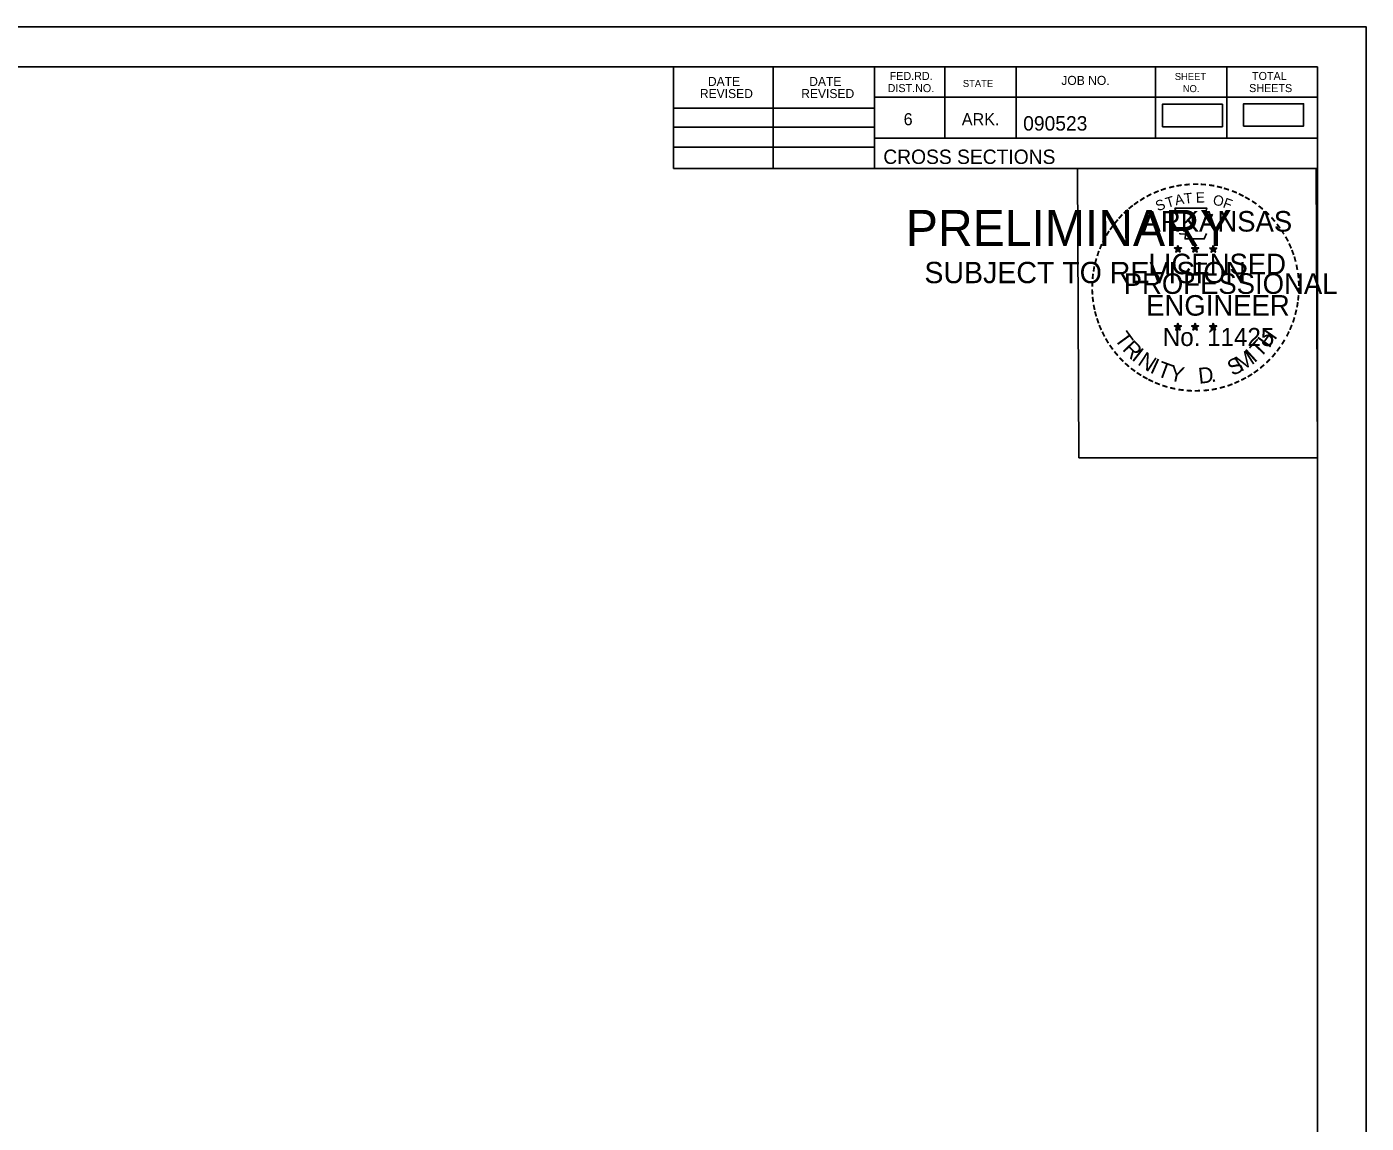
# Model space of a CAD drawing. Extents: x 1406028 to 1412453, y 321733 to 325986.
# Drawn here: x 1406230.5 to 1406360.9, y 322252.5 to 322359.2 of the extents above; entities that cross this region are included whole.
import ezdxf

# ---------------------------------------------------------------- set-up
doc = ezdxf.new("R2010")
doc.units = 0
for name, color, linetype in [('R_Border', 7, 'Continuous'), ('R_Border PE', 7, 'Continuous'), ('R_Border Prem', 7, 'Continuous'), ('R_Fin Surface', 7, 'Continuous'), ('R_No Plot', 7, 'Continuous')]:
    doc.layers.add(name, color=color, linetype=linetype)

msp = doc.modelspace()

# ---------------------------------------------------------------- linework, layer by layer
at = {"layer": 'R_Border'}
for p, q in [((1406039.95, 322355.29), (1406356.13, 322355.29)), ((1406293.49, 322345.41), (1406293.49, 322355.29)), ((1406303.17, 322345.41), (1406303.17, 322355.29)), ((1406313.03, 322355.29), (1406313.03, 322345.41)), ((1406319.87, 322355.29), (1406319.87, 322348.35)), ((1406326.81, 322355.29), (1406326.81, 322348.35)), ((1406340.39, 322355.29), (1406340.39, 322348.35)), ((1406347.33, 322355.29), (1406347.33, 322348.35)), ((1406356.13, 322149.83), (1406356.13, 322355.29)), ((1406356.13, 322352.35), (1406313.03, 322352.35)), ((1406356.13, 322352.37), (1406356.13, 322352.37)), ((1406293.49, 322351.27), (1406313.03, 322351.27)), ((1406293.49, 322349.41), (1406313.03, 322349.41)), ((1406356.13, 322348.35), (1406313.03, 322348.35)), ((1406315.99, 322348.35), (1406356.13, 322348.35)), ((1406293.49, 322347.47), (1406313.03, 322347.47)), ((1406356.13, 322345.41), (1406293.49, 322345.41))]:
    msp.add_line(p, q, dxfattribs=at)
at = {"layer": 'R_Border PE'}
for p, q in [((1406342.21, 322337.67), (1406342.56, 322337.55)), ((1406342.21, 322337.67), (1406342.47, 322337.62)), ((1406342.21, 322337.67), (1406342.45, 322337.54)), ((1406342.56, 322337.92), (1406342.52, 322337.67)), ((1406342.56, 322337.55), (1406342.56, 322337.92)), ((1406342.56, 322337.92), (1406342.61, 322337.67)), ((1406342.91, 322337.67), (1406342.56, 322337.55)), ((1406342.91, 322337.67), (1406342.62, 322337.62)), ((1406342.91, 322337.67), (1406342.7, 322337.56)), ((1406343.88, 322337.67), (1406344.23, 322337.55)), ((1406343.88, 322337.67), (1406344.14, 322337.62)), ((1406343.88, 322337.67), (1406344.12, 322337.54)), ((1406344.23, 322337.92), (1406344.19, 322337.67)), ((1406344.23, 322337.55), (1406344.23, 322337.92)), ((1406344.23, 322337.92), (1406344.28, 322337.67)), ((1406344.58, 322337.67), (1406344.23, 322337.55)), ((1406344.58, 322337.67), (1406344.29, 322337.62)), ((1406344.58, 322337.67), (1406344.37, 322337.56)), ((1406345.65, 322337.65), (1406346, 322337.54)), ((1406345.65, 322337.65), (1406345.9, 322337.61)), ((1406345.65, 322337.65), (1406345.88, 322337.53)), ((1406346, 322337.91), (1406345.95, 322337.66)), ((1406346, 322337.54), (1406346, 322337.91)), ((1406346, 322337.91), (1406346.04, 322337.66)), ((1406346.34, 322337.65), (1406346, 322337.54)), ((1406346.34, 322337.65), (1406346.06, 322337.6)), ((1406346.34, 322337.65), (1406346.14, 322337.55)), ((1406342.35, 322337.26), (1406342.56, 322337.55)), ((1406342.35, 322337.26), (1406342.47, 322337.5)), ((1406342.35, 322337.26), (1406342.56, 322337.47)), ((1406342.77, 322337.26), (1406342.56, 322337.55)), ((1406342.77, 322337.26), (1406342.56, 322337.47)), ((1406342.77, 322337.26), (1406342.64, 322337.55)), ((1406344.02, 322337.26), (1406344.23, 322337.55)), ((1406344.02, 322337.26), (1406344.14, 322337.5)), ((1406344.02, 322337.26), (1406344.23, 322337.47)), ((1406344.44, 322337.26), (1406344.23, 322337.55)), ((1406344.44, 322337.26), (1406344.23, 322337.47)), ((1406344.44, 322337.26), (1406344.31, 322337.55)), ((1406345.78, 322337.25), (1406346, 322337.54)), ((1406345.78, 322337.25), (1406345.91, 322337.49)), ((1406345.78, 322337.25), (1406345.99, 322337.46)), ((1406346.21, 322337.25), (1406345.99, 322337.46)), ((1406346.21, 322337.25), (1406346, 322337.54)), ((1406346.21, 322337.25), (1406346.07, 322337.54)), ((1406342.21, 322330.09), (1406342.56, 322329.98)), ((1406342.21, 322330.09), (1406342.46, 322330.05)), ((1406342.21, 322330.09), (1406342.45, 322329.97)), ((1406342.34, 322329.68), (1406342.56, 322329.98)), ((1406342.34, 322329.68), (1406342.47, 322329.93)), ((1406342.34, 322329.68), (1406342.56, 322329.9)), ((1406342.56, 322330.35), (1406342.52, 322330.09)), ((1406342.56, 322329.98), (1406342.56, 322330.35)), ((1406342.56, 322330.35), (1406342.61, 322330.1)), ((1406342.9, 322330.09), (1406342.56, 322329.98)), ((1406342.77, 322329.68), (1406342.56, 322329.98)), ((1406342.77, 322329.68), (1406342.56, 322329.9)), ((1406342.9, 322330.09), (1406342.62, 322330.04)), ((1406342.77, 322329.68), (1406342.63, 322329.98)), ((1406342.9, 322330.09), (1406342.7, 322329.99)), ((1406343.88, 322330.09), (1406344.23, 322329.98)), ((1406343.88, 322330.09), (1406344.13, 322330.05)), ((1406343.88, 322330.09), (1406344.11, 322329.97)), ((1406344.01, 322329.68), (1406344.23, 322329.98)), ((1406344.01, 322329.68), (1406344.14, 322329.93)), ((1406344.01, 322329.68), (1406344.22, 322329.9)), ((1406344.23, 322330.35), (1406344.19, 322330.09)), ((1406344.44, 322329.68), (1406344.22, 322329.9)), ((1406344.23, 322329.98), (1406344.23, 322330.35)), ((1406344.23, 322330.35), (1406344.28, 322330.1)), ((1406344.57, 322330.09), (1406344.23, 322329.98)), ((1406344.44, 322329.68), (1406344.23, 322329.98)), ((1406344.57, 322330.09), (1406344.29, 322330.04)), ((1406344.44, 322329.68), (1406344.3, 322329.98)), ((1406344.57, 322330.09), (1406344.37, 322329.99)), ((1406345.64, 322330.08), (1406345.99, 322329.97)), ((1406345.64, 322330.08), (1406345.9, 322330.04)), ((1406345.64, 322330.08), (1406345.88, 322329.96)), ((1406345.78, 322329.67), (1406345.99, 322329.97)), ((1406345.78, 322329.67), (1406345.9, 322329.92)), ((1406345.78, 322329.67), (1406345.99, 322329.89)), ((1406345.99, 322330.34), (1406345.95, 322330.08)), ((1406345.99, 322329.97), (1406345.99, 322330.34)), ((1406345.99, 322330.34), (1406346.04, 322330.09)), ((1406346.34, 322330.08), (1406345.99, 322329.97)), ((1406346.21, 322329.67), (1406345.99, 322329.97)), ((1406346.21, 322329.67), (1406345.99, 322329.89)), ((1406346.34, 322330.08), (1406346.05, 322330.03)), ((1406346.21, 322329.67), (1406346.07, 322329.97)), ((1406346.34, 322330.08), (1406346.14, 322329.98))]:
    msp.add_line(p, q, dxfattribs=at)
for points in [[(1406342.25, 322341.54), (1406342.52, 322340.72)], [(1406345.76, 322340.62), (1406345.91, 322340.91), (1406345.22, 322340.88), (1406345.37, 322341.54), (1406342.25, 322341.54)], [(1406342.75, 322339.12), (1406342.75, 322339.03), (1406343.31, 322339.01), (1406343.25, 322338.54), (1406345.12, 322338.54), (1406345.33, 322339.08)], [(1406342.56, 322337.92), (1406342.77, 322337.26), (1406342.21, 322337.67), (1406342.91, 322337.67), (1406342.35, 322337.26), (1406342.56, 322337.92)], [(1406344.23, 322337.92), (1406344.44, 322337.26), (1406343.88, 322337.67), (1406344.58, 322337.67), (1406344.02, 322337.26), (1406344.23, 322337.92)], [(1406346, 322337.91), (1406346.21, 322337.25), (1406345.65, 322337.65), (1406346.34, 322337.65), (1406345.78, 322337.25), (1406346, 322337.91)], [(1406342.56, 322330.35), (1406342.77, 322329.68), (1406342.21, 322330.09), (1406342.9, 322330.09), (1406342.34, 322329.68), (1406342.56, 322330.35)], [(1406344.23, 322330.35), (1406344.44, 322329.68), (1406343.88, 322330.09), (1406344.57, 322330.09), (1406344.01, 322329.68), (1406344.23, 322330.35)], [(1406345.99, 322330.34), (1406346.21, 322329.67), (1406345.64, 322330.08), (1406346.34, 322330.08), (1406345.78, 322329.67), (1406345.99, 322330.34)]]:
    msp.add_lwpolyline(points, dxfattribs=at)
for centre, radius in [((1406342.56, 322337.55), 0.172), ((1406342.56, 322337.55), 0.145), ((1406342.56, 322337.55), 0.116), ((1406342.56, 322337.55), 0.0991), ((1406342.56, 322337.55), 0.0747), ((1406342.56, 322337.55), 0.0495), ((1406342.56, 322337.55), 0.0296), ((1406344.23, 322337.55), 0.172), ((1406344.23, 322337.55), 0.145), ((1406344.23, 322337.55), 0.116), ((1406344.23, 322337.55), 0.0991), ((1406344.23, 322337.55), 0.0747), ((1406344.23, 322337.55), 0.0495), ((1406344.23, 322337.55), 0.0296), ((1406345.99, 322337.54), 0.172), ((1406345.99, 322337.54), 0.145), ((1406345.99, 322337.54), 0.116), ((1406345.99, 322337.54), 0.0991), ((1406345.99, 322337.54), 0.0747), ((1406345.99, 322337.54), 0.0495), ((1406345.99, 322337.54), 0.0296), ((1406342.56, 322329.98), 0.172), ((1406342.56, 322329.98), 0.145), ((1406342.56, 322329.98), 0.116), ((1406342.56, 322329.98), 0.0991), ((1406342.56, 322329.98), 0.0747), ((1406342.56, 322329.98), 0.0495), ((1406342.56, 322329.98), 0.0296), ((1406344.23, 322329.98), 0.172), ((1406344.23, 322329.98), 0.145), ((1406344.23, 322329.98), 0.116), ((1406344.23, 322329.98), 0.0991), ((1406344.23, 322329.98), 0.0747), ((1406344.23, 322329.98), 0.0495), ((1406344.23, 322329.98), 0.0296), ((1406345.99, 322329.97), 0.172), ((1406345.99, 322329.97), 0.145), ((1406345.99, 322329.97), 0.116), ((1406345.99, 322329.97), 0.0991), ((1406345.99, 322329.97), 0.0747), ((1406345.99, 322329.97), 0.0495), ((1406345.99, 322329.97), 0.0296)]:
    msp.add_circle(centre, radius, dxfattribs=at)
at = {"layer": 'R_Fin Surface'}
for points in [[(1406341.05, 322349.46), (1406346.88, 322349.46), (1406346.88, 322351.65), (1406341.05, 322351.65)], [(1406348.94, 322349.52), (1406354.78, 322349.52), (1406354.78, 322351.7), (1406348.94, 322351.7)]]:
    msp.add_lwpolyline(points, close=True, dxfattribs=at)
at = {"layer": 'R_No Plot'}
for p, q in [((1406027.55, 322359.18), (1406360.88, 322359.18)), ((1406332.16, 322322.95), (1406332.16, 322322.95))]:
    msp.add_line(p, q, dxfattribs=at)
for points in [[(1406027.54, 322359.18), (1406360.88, 322359.18), (1406360.88, 322145.85), (1406027.54, 322145.85)], [(1406273.87, 322355.29), (1406293.49, 322355.29), (1406293.49, 322345.41), (1406309.6, 322345.41), (1406332.8, 322345.41), (1406332.92, 322317.25), (1406356.13, 322317.25), (1406356.13, 322149.83), (1406039.95, 322149.83), (1406039.95, 322355.29)], [(1406332.8, 322345.41), (1406356.01, 322345.41), (1406356.13, 322317.25), (1406332.92, 322317.25)]]:
    msp.add_lwpolyline(points, close=True, dxfattribs=at)

# ---------------------------------------------------------------- texts
at = {"layer": 'R_Border'}
for s, height, p in [('FED.RD.', 0.782, (1406314.51, 322354.01)), ('SHEET', 0.684, (1406342.25, 322354.01)), ('TOTAL', 0.782, (1406349.77, 322354.01)), ('DATE', 0.879, (1406296.82, 322353.43)), ('DATE', 0.879, (1406306.68, 322353.43)), ('DIST.NO.', 0.782, (1406314.31, 322352.83)), ('STATE', 0.684, (1406321.63, 322353.33)), ('JOB NO.', 0.879, (1406331.21, 322353.53)), ('NO.', 0.684, (1406343.03, 322352.83)), ('SHEETS', 0.782, (1406349.49, 322352.83)), ('REVISED', 0.879, (1406296.04, 322352.25)), ('REVISED', 0.879, (1406305.9, 322352.25)), ('6', 1.17, (1406315.87, 322349.61)), ('ARK.', 1.172, (1406321.53, 322349.61)), ('090523', 1.4, (1406327.5, 322349.09)), ('CROSS SECTIONS', 1.4, (1406313.89, 322345.84))]:
    msp.add_text(s, height=height, rotation=360, dxfattribs=at).set_placement(p)
at = {"layer": 'R_Border PE'}
for s, height, rotation, p in [('-', 1.6, 28.7918, (1406339.73, 322342.08)), ('-', 1.6, 24.3072, (1406340.37, 322342.4)), ('-', 1.6, 19.1761, (1406341, 322342.67)), ('-', 1.6, 13.6301, (1406341.75, 322342.91)), ('A', 1, 11.2132, (1406342.35, 322341.8)), ('-', 1.6, 10.2193, (1406342.43, 322343.07)), ('T', 1, 6.0228, (1406343.2, 322341.97)), ('-', 1.6, 5.8968, (1406343.16, 322343.18)), ('-', 1.6, 0.1862, (1406343.93, 322343.26)), ('E', 1, 0.8323, (1406344.3, 322342.08)), ('-', 1.6, 357.743, (1406344.65, 322343.24)), ('-', 1.6, 352.1617, (1406345.4, 322343.19)), ('O', 1, 350.4515, (1406345.91, 322341.87)), ('-', 1.6, 347.2049, (1406346.12, 322343.07)), ('-', 1.6, 342.3362, (1406346.75, 322342.92)), ('-', 1.6, 337.8551, (1406347.49, 322342.69)), ('-', 1.6, 334.1211, (1406348.12, 322342.42)), ('-', 1.6, 38.9507, (1406338.08, 322340.94)), ('-', 1.6, 36.2317, (1406338.56, 322341.32)), ('-', 1.6, 34.0636, (1406339.14, 322341.71)), ('S', 1, 21.594, (1406340.61, 322341.22)), ('T', 1, 16.4036, (1406341.52, 322341.55)), ('F', 1, 340.0707, (1406346.86, 322341.64)), ('-', 1.6, 329.6409, (1406348.7, 322342.14)), ('-', 1.6, 325.8627, (1406349.34, 322341.78)), ('-', 1.6, 320.5297, (1406349.95, 322341.35)), ('-', 1.6, 50.6142, (1406336.8, 322339.56)), ('-', 1.6, 48.423, (1406337.2, 322340.05)), ('-', 1.6, 42.9622, (1406337.65, 322340.52)), ('ARKANSAS', 2, 360, (1406339.11, 322339.26)), ('-', 1.6, 315.5786, (1406350.55, 322340.87)), ('-', 1.6, 309.8797, (1406351.12, 322340.32)), ('-', 1.6, 58.0706, (1406336.06, 322338.47)), ('-', 1.6, 54.2325, (1406336.39, 322338.99)), ('-', 1.6, 306.6522, (1406351.64, 322339.71)), ('-', 1.4, 303.6753, (1406352.13, 322339.15)), ('-', 1.6, 67.7743, (1406335.49, 322337.24)), ('-', 1.6, 62.8713, (1406335.75, 322337.85)), ('-', 1.6, 299.6684, (1406352.45, 322338.54)), ('-', 1.6, 294.6628, (1406352.77, 322337.93)), ('-', 1.6, 75.461, (1406335.07, 322335.9)), ('-', 1.6, 72.3945, (1406335.27, 322336.61)), ('LICENSED', 2, 360, (1406339.7, 322335.11)), ('DWB', 0.01, 360, (1406342.55, 322337.55)), ('DWB', 0.01, 360, (1406344.22, 322337.55)), ('DWB', 0.01, 360, (1406345.98, 322337.54)), ('-', 1.6, 290.5728, (1406353.03, 322337.35)), ('-', 1.6, 285.1233, (1406353.26, 322336.77)), ('-', 1.6, 85.1863, (1406334.86, 322334.49)), ('-', 1.6, 81.2013, (1406334.94, 322335.18)), ('PROFESSIONAL', 2, 360, (1406337.28, 322333.2)), ('-', 1.6, 280.5493, (1406353.46, 322336.03)), ('-', 1.6, 276.5962, (1406353.62, 322335.26)), ('-', 1.6, 89.0622, (1406334.84, 322333.79)), ('-', 1.6, 274.3301, (1406353.68, 322334.54)), ('-', 1.6, 269.9407, (1406353.72, 322333.91)), ('-', 1.6, 94.1959, (1406334.87, 322333.07)), ('-', 1.6, 98.9479, (1406334.95, 322332.4)), ('ENGINEER', 2, 360, (1406339.47, 322331.08)), ('-', 1.6, 260.9953, (1406353.63, 322332.59)), ('-', 1.6, 263.5172, (1406353.7, 322333.24)), ('-', 1.6, 101.7149, (1406335.08, 322331.67)), ('-', 1.6, 105.4578, (1406335.24, 322331.07)), ('-', 1.6, 255.7626, (1406353.52, 322331.91)), ('-', 1.6, 109.0874, (1406335.46, 322330.44)), ('-', 1.6, 114.0643, (1406335.71, 322329.85)), ('No. 11425', 1.757, 360, (1406341.09, 322328.13)), ('DWB', 0.01, 360, (1406342.54, 322329.98)), ('DWB', 0.01, 360, (1406344.21, 322329.98)), ('DWB', 0.01, 360, (1406345.98, 322329.97)), ('H', 1.54, 54.6088, (1406351.44, 322327.85)), ('-', 1.6, 247.8887, (1406353.11, 322330.51)), ('-', 1.6, 252.8681, (1406353.34, 322331.19)), ('-', 1.6, 115.7289, (1406336.02, 322329.23)), ('-', 1.6, 120.4471, (1406336.37, 322328.64)), ('T', 1.54, 306.0406, (1406336.32, 322328.82)), ('R', 1.54, 314.005, (1406337.08, 322327.77)), ('T', 1.54, 46.6444, (1406350.55, 322326.91)), ('-', 1.6, 239.0712, (1406352.46, 322329.13)), ('-', 1.6, 244.6197, (1406352.85, 322329.89)), ('-', 1.6, 125.8934, (1406336.78, 322328.08)), ('-', 1.6, 130.7181, (1406337.24, 322327.53)), ('I', 1.54, 321.9694, (1406337.98, 322326.84)), ('N', 1.54, 326.5002, (1406338.55, 322326.37)), ('M', 1.54, 32.6563, (1406348.7, 322325.59)), ('I', 1.54, 42.1136, (1406349.99, 322326.43)), ('-', 1.6, 231.2538, (1406351.63, 322327.91)), ('-', 1.6, 233.8452, (1406352.06, 322328.48)), ('-', 1.6, 134.2238, (1406337.76, 322326.98)), ('-', 1.6, 138.9338, (1406338.28, 322326.52)), ('-', 1.6, 144.6463, (1406338.84, 322326.11)), ('I', 1.54, 335.3603, (1406339.75, 322325.58)), ('T', 1.54, 339.8912, (1406340.42, 322325.25)), ('Y', 1.54, 347.8556, (1406341.63, 322324.81)), ('D', 1.54, 6.3969, (1406344.62, 322324.45)), ('S', 1.54, 26.9312, (1406347.86, 322325.18)), ('-', 1.6, 215.7363, (1406350.08, 322326.37)), ('-', 1.6, 221.0851, (1406350.62, 322326.84)), ('-', 1.6, 225.7653, (1406351.15, 322327.35)), ('-', 1.6, 148.0898, (1406339.4, 322325.74)), ('-', 1.6, 151.5704, (1406339.98, 322325.42)), ('-', 1.6, 154.6002, (1406340.5, 322325.17)), ('-', 1.6, 158.5612, (1406341.12, 322324.92)), ('.', 1.54, 13.7642, (1406345.81, 322324.58)), ('-', 1.6, 204.2516, (1406348.36, 322325.32)), ('-', 1.6, 207.3568, (1406348.98, 322325.64)), ('-', 1.6, 212.2491, (1406349.54, 322325.98)), ('-', 1.6, 162.7983, (1406341.81, 322324.7)), ('-', 1.6, 167.5555, (1406342.53, 322324.54)), ('-', 1.6, 173.1155, (1406343.3, 322324.43)), ('-', 1.6, 176.5183, (1406344.05, 322324.38)), ('-', 1.6, 181.5918, (1406344.79, 322324.4)), ('-', 1.6, 185.8167, (1406345.6, 322324.47)), ('-', 1.6, 191.2858, (1406346.33, 322324.6)), ('-', 1.6, 195.4743, (1406347.06, 322324.8)), ('-', 1.6, 200.7184, (1406347.74, 322325.04))]:
    msp.add_text(s, height=height, rotation=rotation, dxfattribs=at).set_placement(p)
at = {"layer": 'R_Border Prem'}
for s, height, p in [('PRELIMINARY', 3.5, (1406316.08, 322337.87)), ('DWB', 0.01, (1406316.82, 322339.72)), ('SUBJECT TO REVISION', 2.0751, (1406317.89, 322334.24))]:
    msp.add_text(s, height=height, rotation=360, dxfattribs=at).set_placement(p)

doc.saveas('drawing.dxf')
